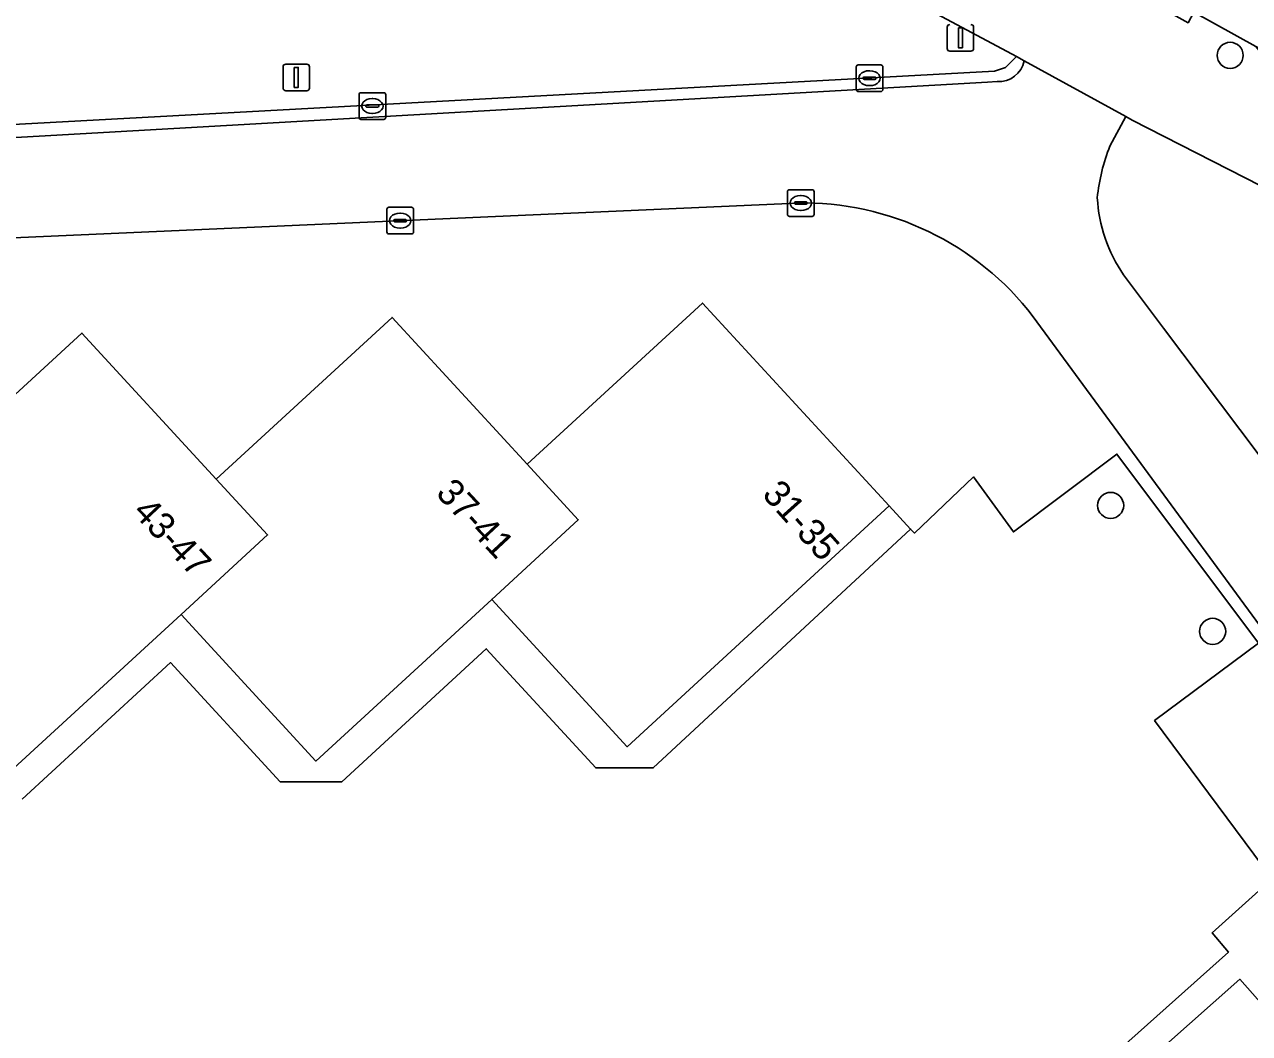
# Model space of a CAD drawing. Extents: x 160349 to 161355, y 381727 to 382854.
# Drawn here: x 160748.06 to 160794.04, y 381912.74 to 381950.61 of the extents above; entities that cross this region are included whole.
import ezdxf

# ---------------------------------------------------------------- set-up
doc = ezdxf.new("R2010")
doc.units = 0
for name, color, linetype in [('IMGEO_Boom', 7, 'Continuous'), ('IMGEO_Groenvoorziening', 7, 'Continuous'), ('IMGEO_Kolk', 7, 'Continuous'), ('IMGEO_Lichtmast', 7, 'Continuous'), ('IMGEO_Pand', 7, 'Continuous'), ('IMGEO_Pand_nummerreeks', 7, 'Continuous'), ('IMGEO_Rijbaan_lokaal_gesloten', 7, 'Continuous'), ('IMGEO_Rijbaan_lokaal_open', 7, 'Continuous'), ('IMGEO_Voetpad_halfverhard', 7, 'Continuous'), ('IMGEO_Voetpad_open', 7, 'Continuous')]:
    doc.layers.add(name, color=color, linetype=linetype)

msp = doc.modelspace()

# ---------------------------------------------------------------- linework, layer by layer
at = {"layer": 'IMGEO_Boom'}
for centre in [(160793.313, 381949.45), (160788.825, 381932.557), (160792.654, 381927.831)]:
    msp.add_circle(centre, 0.489, dxfattribs=at)
at = {"layer": 'IMGEO_Groenvoorziening'}
for points in [[(160742.562, 381946.583), (160784.463, 381948.856), (160784.875, 381948.991), (160785.29, 381949.403), (160745.256, 381970.771), (160720.104, 381951.115), (160692.7, 381919.619), (160701.529, 381916.873), (160703.013, 381918.224), (160702.637, 381918.693), (160703.65, 381919.616), (160704.036, 381919.156), (160707.061, 381921.911), (160728.881, 381942.036), (160727.68, 381942.609), (160726.588, 381943.368)], [(160830.732, 381924.65), (160831.29, 381925.762), (160789.629, 381947.019), (160789.391, 381947.15), (160788.797, 381946.047)], [(160789.31, 381941.209), (160790.814, 381939.212), (160801.548, 381924.962)], [(160782.845, 381906.498), (160793.245, 381915.795), (160792.633, 381916.513), (160794.892, 381918.548), (160790.477, 381924.479), (160794.37, 381927.389), (160789.06, 381934.483), (160785.176, 381931.56), (160783.677, 381933.625), (160781.459, 381931.518), (160781.317, 381931.671), (160771.659, 381922.705), (160769.498, 381922.705), (160765.386, 381927.176), (160759.961, 381922.185), (160757.648, 381922.185), (160753.532, 381926.659), (160747.962, 381921.535)]]:
    msp.add_lwpolyline(points, dxfattribs=at)
for centre, radius, start, end in [((160795.516, 381943.382), 7.228, 158.3673, 174.2691), ((160794.009, 381944.425), 5.694, 183.2287, 214.3877)]:
    msp.add_arc(centre, radius, start, end, dxfattribs=at)
at = {"layer": 'IMGEO_Kolk'}
for p, q in [((160779.348, 381949.092), (160780.2, 381949.092)), ((160779.273, 381948.166), (160779.273, 381949.018)), ((160779.532, 381948.586), (160779.532, 381948.598)), ((160779.575, 381948.635), (160779.973, 381948.635)), ((160779.761, 381948.872), (160779.786, 381948.872)), ((160780.016, 381948.598), (160780.016, 381948.586)), ((160780.274, 381949.018), (160780.274, 381948.166)), ((160779.97, 381948.549), (160779.572, 381948.549)), ((160779.784, 381948.312), (160779.759, 381948.312)), ((160760.611, 381947.12), (160760.611, 381947.972)), ((160760.686, 381948.046), (160761.538, 381948.046)), ((160761.099, 381947.826), (160761.124, 381947.826)), ((160761.612, 381947.972), (160761.612, 381947.12)), ((160780.2, 381948.092), (160779.348, 381948.092)), ((160760.87, 381947.54), (160760.87, 381947.552)), ((160761.308, 381947.503), (160760.91, 381947.503)), ((160760.913, 381947.589), (160761.311, 381947.589)), ((160761.122, 381947.266), (160761.097, 381947.266)), ((160761.354, 381947.552), (160761.354, 381947.54)), ((160761.538, 381947.046), (160760.686, 381947.046)), ((160776.694, 381943.481), (160776.694, 381944.333)), ((160776.769, 381944.407), (160777.621, 381944.407)), ((160777.182, 381944.187), (160777.207, 381944.187)), ((160777.695, 381944.333), (160777.695, 381943.481)), ((160761.657, 381942.82), (160761.657, 381943.672)), ((160761.732, 381943.746), (160762.584, 381943.746)), ((160762.145, 381943.526), (160762.17, 381943.526)), ((160762.658, 381943.672), (160762.658, 381942.82)), ((160776.953, 381943.901), (160776.953, 381943.913)), ((160777.391, 381943.864), (160776.993, 381943.864)), ((160776.996, 381943.95), (160777.394, 381943.95)), ((160777.205, 381943.627), (160777.18, 381943.627)), ((160777.437, 381943.913), (160777.437, 381943.901)), ((160761.916, 381943.24), (160761.916, 381943.252)), ((160762.354, 381943.203), (160761.956, 381943.203)), ((160761.959, 381943.289), (160762.357, 381943.289)), ((160762.4, 381943.252), (160762.4, 381943.24)), ((160777.621, 381943.407), (160776.769, 381943.407)), ((160762.584, 381942.746), (160761.732, 381942.746)), ((160762.168, 381942.966), (160762.143, 381942.966))]:
    msp.add_line(p, q, dxfattribs=at)
for points in [[(160779.348, 381949.092), (160780.2, 381949.092)], [(160779.273, 381948.166), (160779.273, 381949.018)], [(160780.274, 381949.018), (160780.274, 381948.166)], [(160760.611, 381947.12), (160760.611, 381947.972)], [(160760.686, 381948.046), (160761.538, 381948.046)], [(160761.612, 381947.972), (160761.612, 381947.12)], [(160780.2, 381948.092), (160779.348, 381948.092)], [(160761.538, 381947.046), (160760.686, 381947.046)], [(160776.694, 381943.481), (160776.694, 381944.333)], [(160776.769, 381944.407), (160777.621, 381944.407)], [(160777.695, 381944.333), (160777.695, 381943.481)], [(160761.657, 381942.82), (160761.657, 381943.672)], [(160761.732, 381943.746), (160762.584, 381943.746)], [(160762.658, 381943.672), (160762.658, 381942.82)], [(160777.621, 381943.407), (160776.769, 381943.407)], [(160762.584, 381942.746), (160761.732, 381942.746)]]:
    msp.add_lwpolyline(points, dxfattribs=at)
for centre, radius, start, end in [((160779.35, 381949.016), 0.0765, 91.552, 178.448), ((160779.35, 381949.016), 0.0765, 91.552, 178.448), ((160780.198, 381949.016), 0.0765, 1.552, 88.448), ((160780.198, 381949.016), 0.0765, 1.552, 88.448), ((160779.572, 381948.595), 0.0403, 85.8775, 175.7526), ((160779.569, 381948.585), 0.0366, 178.938, 274.7102), ((160779.973, 381948.592), 0.043, 264.8664, 352.4533), ((160779.977, 381948.597), 0.0386, 1.7309, 96.639), ((160779.35, 381948.168), 0.0765, 181.552, 268.448), ((160779.35, 381948.168), 0.0765, 181.552, 268.448), ((160780.198, 381948.168), 0.0765, 271.552, 358.448), ((160780.198, 381948.168), 0.0765, 271.552, 358.448), ((160760.688, 381947.97), 0.0765, 91.552, 178.448), ((160760.688, 381947.97), 0.0765, 91.552, 178.448), ((160761.536, 381947.97), 0.0765, 1.552, 88.448), ((160761.536, 381947.97), 0.0765, 1.552, 88.448), ((160760.91, 381947.549), 0.0403, 85.8775, 175.7526), ((160760.907, 381947.539), 0.0366, 178.938, 274.7102), ((160761.311, 381947.546), 0.043, 264.8664, 352.4533), ((160761.315, 381947.551), 0.0386, 1.7309, 96.639), ((160760.688, 381947.122), 0.0765, 181.552, 268.448), ((160760.688, 381947.122), 0.0765, 181.552, 268.448), ((160761.536, 381947.122), 0.0765, 271.552, 358.448), ((160761.536, 381947.122), 0.0765, 271.552, 358.448), ((160776.771, 381944.331), 0.0765, 91.552, 178.448), ((160776.771, 381944.331), 0.0765, 91.552, 178.448), ((160777.619, 381944.331), 0.0765, 1.552, 88.448), ((160777.619, 381944.331), 0.0765, 1.552, 88.448), ((160761.734, 381943.67), 0.0765, 91.552, 178.448), ((160761.734, 381943.67), 0.0765, 91.552, 178.448), ((160762.582, 381943.67), 0.0765, 1.552, 88.448), ((160762.582, 381943.67), 0.0765, 1.552, 88.448), ((160776.993, 381943.91), 0.0403, 85.8775, 175.7526), ((160776.99, 381943.9), 0.0366, 178.938, 274.7102), ((160777.394, 381943.907), 0.043, 264.8664, 352.4533), ((160777.398, 381943.912), 0.0386, 1.7309, 96.639), ((160761.956, 381943.249), 0.0403, 85.8775, 175.7526), ((160761.953, 381943.239), 0.0366, 178.938, 274.7102), ((160762.357, 381943.246), 0.043, 264.8664, 352.4533), ((160762.361, 381943.251), 0.0386, 1.7309, 96.639), ((160776.771, 381943.483), 0.0765, 181.552, 268.448), ((160776.771, 381943.483), 0.0765, 181.552, 268.448), ((160777.619, 381943.483), 0.0765, 271.552, 358.448), ((160777.619, 381943.483), 0.0765, 271.552, 358.448), ((160761.734, 381942.822), 0.0765, 181.552, 268.448), ((160761.734, 381942.822), 0.0765, 181.552, 268.448), ((160762.582, 381942.822), 0.0765, 271.552, 358.448), ((160762.582, 381942.822), 0.0765, 271.552, 358.448)]:
    msp.add_arc(centre, radius, start, end, dxfattribs=at)
for centre, major_axis, ratio, start_param, end_param in [((160779.76, 381948.592), (-0.387, 0.002), 0.722429, 4.712389, 7.853982), ((160779.785, 381948.592), (-0.39, 0.002), 0.717154, 1.570796, 4.712389), ((160761.098, 381947.546), (-0.387, 0.002), 0.722429, 4.712389, 7.853982), ((160761.123, 381947.546), (-0.39, 0.002), 0.717154, 1.570796, 4.712389), ((160777.181, 381943.907), (-0.387, 0.002), 0.722429, 4.712389, 7.853982), ((160777.206, 381943.907), (-0.39, 0.002), 0.717154, 1.570796, 4.712389), ((160762.144, 381943.246), (-0.387, 0.002), 0.722429, 4.712389, 7.853982), ((160762.169, 381943.246), (-0.39, 0.002), 0.717154, 1.570796, 4.712389)]:
    msp.add_ellipse(centre, major_axis=major_axis, ratio=ratio, start_param=start_param, end_param=end_param, dxfattribs=at)
at = {"layer": 'IMGEO_Lichtmast'}
for p, q in [((160782.69, 381949.708), (160782.69, 381950.508)), ((160782.69, 381950.508), (160782.69, 381949.708)), ((160783.68, 381950.508), (160783.68, 381949.708)), ((160783.68, 381949.708), (160783.68, 381950.508)), ((160783.58, 381949.608), (160782.79, 381949.608)), ((160782.79, 381949.608), (160783.58, 381949.608)), ((160757.862, 381949.12), (160758.652, 381949.12)), ((160758.652, 381949.12), (160757.862, 381949.12)), ((160757.762, 381948.22), (160757.762, 381949.02)), ((160757.762, 381949.02), (160757.762, 381948.22)), ((160758.752, 381949.02), (160758.752, 381948.22)), ((160758.752, 381948.22), (160758.752, 381949.02)), ((160758.652, 381948.12), (160757.862, 381948.12)), ((160757.862, 381948.12), (160758.652, 381948.12))]:
    msp.add_line(p, q, dxfattribs=at)
for points in [[(160783.11, 381950.483), (160783.26, 381950.483), (160783.26, 381949.733), (160783.11, 381949.733), (160783.11, 381950.483)], [(160758.182, 381948.995), (160758.332, 381948.995), (160758.332, 381948.245), (160758.182, 381948.245), (160758.182, 381948.995)]]:
    msp.add_lwpolyline(points, dxfattribs=at)
for centre, start, end in [((160782.79, 381950.508), 90, 180), ((160782.79, 381950.508), 90, 180), ((160783.58, 381950.508), 0, 90), ((160783.58, 381950.508), 360, 90), ((160782.79, 381949.708), 180, 270), ((160782.79, 381949.708), 180, 270), ((160783.58, 381949.708), 270, 0), ((160783.58, 381949.708), 270, 0), ((160757.862, 381949.02), 90, 180), ((160757.862, 381949.02), 90, 180), ((160758.652, 381949.02), 0, 90), ((160758.652, 381949.02), 360, 90), ((160757.862, 381948.22), 180, 270), ((160757.862, 381948.22), 180, 270), ((160758.652, 381948.22), 270, 0), ((160758.652, 381948.22), 270, 0)]:
    msp.add_arc(centre, 0.1, start, end, dxfattribs=at)
at = {"layer": 'IMGEO_Pand'}
for points in [[(160765.591, 381929.029), (160770.676, 381923.501), (160780.508, 381932.546), (160773.509, 381940.154), (160766.928, 381934.1), (160768.842, 381932.02)], [(160753.932, 381928.46), (160758.993, 381922.959), (160765.591, 381929.029), (160768.842, 381932.02), (160766.928, 381934.1), (160761.854, 381939.616), (160755.254, 381933.544), (160757.181, 381931.449)], [(160753.932, 381928.46), (160757.181, 381931.449), (160755.254, 381933.544), (160750.211, 381939.027), (160743.604, 381932.949), (160745.541, 381930.843), (160742.314, 381927.875), (160747.348, 381922.403)], [(160798.607, 381909.202), (160793.675, 381914.77), (160786.891, 381908.762), (160786.177, 381908.13), (160786.618, 381907.631), (160786.99, 381907.961), (160787.432, 381907.462), (160788.32, 381906.46), (160785.459, 381903.926), (160790.605, 381898.115), (160797.346, 381904.085), (160800.593, 381906.96)]]:
    msp.add_lwpolyline(points, close=True, dxfattribs=at)
at = {"layer": 'IMGEO_Rijbaan_lokaal_gesloten'}
for points in [[(160788.797, 381946.047), (160789.391, 381947.15), (160785.583, 381949.242)], [(160784.563, 381948.466), (160784.208, 381948.446), (160743.104, 381946.105)], [(160730.518, 381942.004), (160733.198, 381941.965), (160777.044, 381943.907)], [(160801.548, 381924.962), (160790.814, 381939.212), (160789.31, 381941.209)], [(160785.918, 381939.64), (160798.596, 381922.37)]]:
    msp.add_lwpolyline(points, dxfattribs=at)
for centre, radius, start, end in [((160784.622, 381949.447), 0.983, 266.5749, 347.9517), ((160795.516, 381943.382), 7.228, 158.3673, 174.2691), ((160794.009, 381944.425), 5.694, 183.2287, 214.3877), ((160777.277, 381933.03), 10.88, 37.4148, 91.2247)]:
    msp.add_arc(centre, radius, start, end, dxfattribs=at)
at = {"layer": 'IMGEO_Rijbaan_lokaal_open'}
msp.add_lwpolyline([(160783.615, 381955.602), (160786.617, 381954.029), (160791.949, 381951.067), (160794.272, 381949.777), (160824.977, 381933.582), (160825.379, 381933.478), (160833.426, 381929.292), (160841.525, 381925.098), (160848.187, 381921.638), (160854.945, 381918.142), (160855.781, 381917.696), (160857.744, 381916.681), (160860.432, 381922.204), (160858.668, 381923.098), (160813.262, 381946.618), (160812.854, 381946.829), (160799.884, 381953.571), (160798.792, 381954.127), (160785.618, 381960.974)], dxfattribs=at)
at = {"layer": 'IMGEO_Voetpad_halfverhard'}
msp.add_lwpolyline([(160747.962, 381921.535), (160753.532, 381926.659), (160757.648, 381922.185), (160759.961, 381922.185), (160765.386, 381927.176), (160769.498, 381922.705), (160771.659, 381922.705), (160781.317, 381931.671), (160780.508, 381932.546), (160770.676, 381923.501), (160765.591, 381929.029), (160758.993, 381922.959), (160753.932, 381928.46), (160747.348, 381922.403)], dxfattribs=at)
at = {"layer": 'IMGEO_Voetpad_open'}
for points in [[(160740.787, 381973.103), (160745.256, 381970.771), (160785.29, 381949.403), (160785.583, 381949.242), (160789.391, 381947.15), (160789.629, 381947.019), (160831.29, 381925.762), (160835.192, 381923.816), (160854.514, 381914.18), (160854.739, 381917.742), (160847.981, 381921.238), (160848.187, 381921.638), (160841.525, 381925.098), (160841.319, 381924.698), (160833.22, 381928.892), (160833.426, 381929.292), (160825.379, 381933.478), (160824.977, 381933.582), (160824.596, 381933.592), (160822.597, 381933.17)], [(160795.169, 381947.617), (160794.71, 381949.12), (160794.503, 381949.502), (160794.272, 381949.777), (160791.949, 381951.067), (160791.731, 381950.673), (160786.399, 381953.635), (160786.617, 381954.029), (160783.615, 381955.602)], [(160785.583, 381949.242), (160785.29, 381949.403), (160784.875, 381948.991), (160784.463, 381948.856), (160742.562, 381946.583)], [(160743.104, 381946.105), (160784.208, 381948.446), (160784.563, 381948.466)], [(160777.044, 381943.907), (160733.198, 381941.965), (160730.518, 381942.004)], [(160726.588, 381943.368), (160727.68, 381942.609), (160728.881, 381942.036), (160707.061, 381921.911), (160704.036, 381919.156), (160703.65, 381919.616), (160702.637, 381918.693), (160703.013, 381918.224), (160701.529, 381916.873), (160702.632, 381916.514), (160704.645, 381915.916), (160705.831, 381919.449), (160719.952, 381932.403), (160720.314, 381932.008), (160726.776, 381937.953), (160731.902, 381932.381), (160738.523, 381938.472), (160743.604, 381932.949), (160750.211, 381939.027)], [(160750.211, 381939.027), (160755.254, 381933.544), (160761.854, 381939.616), (160766.928, 381934.1), (160773.509, 381940.154), (160780.508, 381932.546), (160781.317, 381931.671), (160781.459, 381931.518), (160783.677, 381933.625), (160785.176, 381931.56), (160789.06, 381934.483), (160794.37, 381927.389), (160790.477, 381924.479), (160794.892, 381918.548), (160792.633, 381916.513), (160793.245, 381915.795), (160782.845, 381906.498)], [(160798.596, 381922.37), (160785.918, 381939.64)], [(160786.891, 381908.762), (160793.675, 381914.77), (160798.607, 381909.202)]]:
    msp.add_lwpolyline(points, dxfattribs=at)
for centre, radius, start, end in [((160784.622, 381949.447), 0.983, 266.5749, 347.9517), ((160777.277, 381933.03), 10.88, 37.4148, 91.2247)]:
    msp.add_arc(centre, radius, start, end, dxfattribs=at)

# ---------------------------------------------------------------- texts
at = {"layer": 'IMGEO_Pand_nummerreeks'}
for s, rotation, p in [('37-41', 313.0475, (160763.457, 381932.986)), ('31-35', 311.9152, (160775.704, 381932.945)), ('43-47', 313.0475, (160752.079, 381932.28))]:
    msp.add_text(s, height=1, rotation=rotation, dxfattribs=at).set_placement(p)

doc.saveas('drawing.dxf')
